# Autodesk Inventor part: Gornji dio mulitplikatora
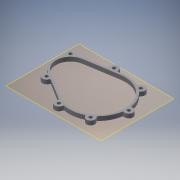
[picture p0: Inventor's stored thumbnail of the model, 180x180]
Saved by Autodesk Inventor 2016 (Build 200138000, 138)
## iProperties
Created: 2015-08
Part Number: Gornji dio mulitplikatora
Material: Generic
Document SubType Name: Modeling
Designer: stank
Density: 1 g/cm^3
Appearance: Default
Author: stank
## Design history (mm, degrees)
workplane "Work Plane1"
sketch "Sketch1"
  geometry: L1 (-33.028, 42.698)-(27.802, -9.971) reference; L2 (-79.077, -68.402)-(-90.579, 11.235) reference; L3 (-95.528, 10.521)-(-95.242, 8.541) reference; L4 (-100.047, 6.837)-(-96.088, 7.409) reference; L5 (-93.23, -12.386)-(-97.189, -12.958) reference; L6 (-92.097, -13.233)-(-84.026, -69.117) reference; L7 (-84.078, -73.704)-(-87.967, -75.12) reference; L8 (-81.127, -93.914)-(-77.237, -92.498) reference; L9 (-42.558, -124.275)-(-43.63, -128.273) reference; L10 (-24.311, -133.45)-(-23.24, -129.452) reference; L11 (22.682, -119.271)-(25.342, -122.442) reference; L12 (40.663, -109.586)-(38.003, -106.415) reference; L13 (56.003, -62.959)-(60.126, -62.599) reference; L14 (58.383, -42.675)-(54.26, -43.035) reference; L15 (31.075, -6.191)-(23.921, 0.004) reference; L16 (23.819, 1.415)-(26.437, 4.439) reference; L17 (11.317, 17.53)-(8.699, 14.506) reference; L18 (7.289, 14.405)-(-29.755, 46.478) reference; L19 (-42.165, 58.93)-(-42.534, 54.713) reference; L20 (-62.458, 56.457)-(-62.089, 60.673) reference; C1 r 4 at (-52.127, 59.802) reference; C2 r 4 at (18.877, 10.984) reference; C3 r 4 at (-98.618, -3.06) reference; C4 r 4 at (-84.547, -84.517) reference; C5 r 4 at (-33.97, -130.862) reference; C6 r 4 at (33.003, -116.014) reference; C7 r 4 at (59.255, -52.637) reference; A1 r 35 centre (-55.938, 16.238) between (-33.028, 42.698) and (-90.579, 11.235) reference; A2 r 65 centre (-14.745, -59.111) between (-79.077, -68.402) and (27.802, -9.971) reference; A3 r 40 centre (-55.938, 16.238) between (-63.271, 55.561) and (-95.528, 10.521) reference; A4 r 1 centre (-96.231, 8.398) between (-96.088, 7.409) and (-95.242, 8.541) reference; A5 r 10 centre (-98.618, -3.06) between (-100.047, 6.837) and (-97.189, -12.958) reference; A6 r 1 centre (-93.087, -13.376) between (-92.097, -13.233) and (-93.23, -12.386) reference; A7 r 70 centre (-14.745, -59.111) between (-84.026, -69.117) and (-83.438, -72.572) reference; A8 r 1 centre (-84.42, -72.764) between (-84.078, -73.704) and (-83.438, -72.572) reference; A9 r 10 centre (-84.547, -84.517) between (-87.967, -75.12) and (-81.127, -93.914) reference; A10 r 1 centre (-76.895, -93.437) between (-76.02, -92.954) and (-77.237, -92.498) reference; A11 r 70 centre (-14.745, -59.111) between (-76.02, -92.954) and (-43.119, -123.102) reference; A12 r 1 centre (-43.524, -124.016) between (-42.558, -124.275) and (-43.119, -123.102) reference; A13 r 10 centre (-33.97, -130.862) between (-43.63, -128.273) and (-24.311, -133.45) reference; A14 r 1 centre (-22.274, -129.71) between (-22.168, -128.716) and (-23.24, -129.452) reference; A15 r 70 centre (-14.745, -59.111) between (-22.168, -128.716) and (21.399, -119.057) reference; A16 r 1 centre (21.916, -119.914) between (22.682, -119.271) and (21.399, -119.057) reference; A17 r 10 centre (33.003, -116.014) between (25.342, -122.442) and (40.663, -109.586) reference; A18 r 1 centre (38.769, -105.772) between (38.015, -105.115) and (38.003, -106.415) reference; A19 r 70 centre (-14.745, -59.111) between (38.015, -105.115) and (55.092, -63.887) reference; A20 r 1 centre (56.09, -63.955) between (56.003, -62.959) and (55.092, -63.887) reference; A21 r 10 centre (59.255, -52.637) between (60.126, -62.599) and (58.383, -42.675) reference; A22 r 1 centre (54.172, -42.039) between (53.202, -42.28) and (54.26, -43.035) reference; A23 r 70 centre (-14.745, -59.111) between (53.202, -42.28) and (31.075, -6.191) reference; A24 r 1 centre (24.575, 0.76) between (23.819, 1.415) and (23.921, 0.004) reference; A25 r 10 centre (18.877, 10.984) between (26.437, 4.439) and (11.317, 17.53) reference; A26 r 1 centre (7.943, 15.161) between (7.289, 14.405) and (8.699, 14.506) reference; A27 r 40 centre (-55.938, 16.238) between (-29.755, 46.478) and (-41.889, 53.69) reference; A28 r 1 centre (-41.538, 54.626) between (-42.534, 54.713) and (-41.889, 53.69) reference; A29 r 10 centre (-52.127, 59.802) between (-42.165, 58.93) and (-62.089, 60.673) reference; A30 r 1 centre (-63.454, 56.544) between (-63.271, 55.561) and (-62.458, 56.457) reference; 1 further point
extrude "Extrusion1" new body sketch "Sketch1" distance "d0" = 6; taper "d1" = 0 deg
sketch "Sketch2"
  geometry: L1 (-42.698, -33.028)-(9.971, 27.802) reference; L2 (68.402, -79.077)-(-11.235, -90.579) reference; C1 r 10 at (57.817, -12.389) reference; C2 r 11 at (57.817, -12.389); A1 r 65 centre (59.111, -14.745) between (68.402, -79.077) and (9.971, 27.802) reference; A2 r 35 centre (-16.238, -55.938) between (-42.698, -33.028) and (-11.235, -90.579) reference; 1 further point
  constraints: 1 centre point, 1 coincident
  dimensions: "d4" = 1 radial gap between concentric circles of C2 C1
extrude "Extrusion4" join sketch "Sketch2" distance "d7" = 5; taper "d8" = -45 deg
sketch "Sketch4"
  geometry: C1 r 23.5 at (11.642, -52.082) reference; C2 r 23.5 at (-57.817, -12.389) reference; C3 r 12.5 at (-57.817, -12.389) reference; C4 r 13.5 at (-57.817, -12.389); C5 r 12.5 at (11.642, -52.082) reference; C6 r 13.5 at (11.642, -52.082); 1 further point
  constraints: 2 centre point, 2 coincident
  dimensions: "d9" = 1 radial gap between concentric circles of C3 C4; "d10" = 1 radial gap between concentric circles of C5 C6
extrude "Extrusion5" join sketch "Sketch4" distance "d11" = 1; taper "d12" = 0 deg
fillet "Fillet1" dims "d13" = 1
sketch "Sketch5"
  geometry: C1 r 23.5 at (11.642, -52.082) reference; C2 r 23.5 at (-57.817, -12.389) reference; C3 r 26.5 at (11.642, -52.082); C4 r 26.5 at (-57.817, -12.389); 1 further point
  constraints: 2 centre point, 2 coincident
  dimensions: "d14" = 3 radial gap between concentric circles of C2 C4; "d15" = 3 radial gap between concentric circles of C3 C1
extrude "Extrusion6" join sketch "Sketch5" distance "d16" = 13; taper "d17" = 0 deg
fillet "Fillet2" dims "d18" = 1
chamfer "Chamfer1" distance "d19" = 1; stored, may be unused: second distance "d20" = 2, angle "d21" = 45 deg
fillet "Fillet3" dims "d22" = 1
fillet "Fillet4" dims "d23" = 5
body "Solid1"
node "Reference1"
node "Reference2"
node "Reference3"
node "Reference4"
node "Reference5"
node "Reference6"
node "Reference7"
node "Reference8"
